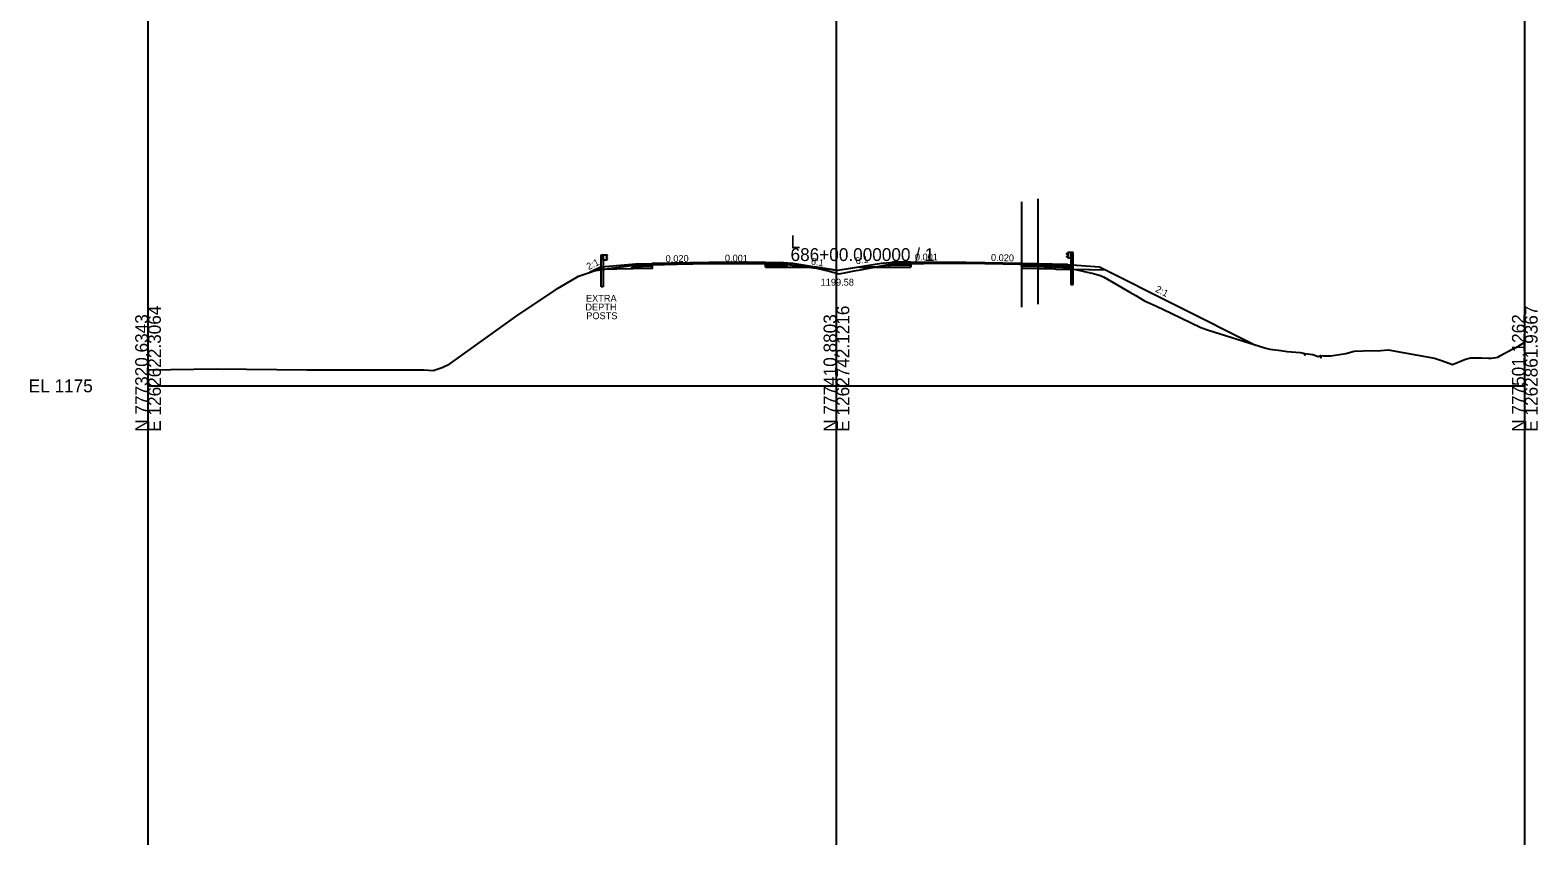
# Model space of a CAD drawing. Extents: x -41 to 1262860, y -100 to 777489.
# Drawn here: x 974.3 to 1302.8, y 1420 to 1597.5 of the extents above; entities that cross this region are included whole.
import ezdxf

# ---------------------------------------------------------------- set-up
doc = ezdxf.new("R2010")
doc.units = 0
for name, color, linetype in [('Exist Cross Section Cell', 7, 'Continuous'), ('Exist XS Center Line Elevation Label', 7, 'Continuous'), ('Exist XS Ground Line', 7, 'Continuous'), ('Prop CMT Guardrail Graphics', 7, 'Continuous'), ('Prop CMT Pvmt Course 1', 7, 'Continuous'), ('Prop CMT Pvmt Surface', 7, 'Continuous'), ('Prop CMT Shld Paved Course 1', 7, 'Continuous'), ('Prop CMT Shld Paved Course 2', 7, 'Continuous'), ('Prop CMT Shld Paved Course 4', 7, 'Continuous'), ('Prop CMT Subgrade Earthwork', 7, 'Continuous'), ('Prop XS Earthwork Shape', 7, 'Continuous'), ('Prop XS Exc Vertical Line 1', 7, 'Continuous'), ('Prop XS Exc Vertical Line 2', 7, 'Continuous'), ('Prop XS Exc Vertical Line 3', 7, 'Continuous'), ('Prop XS Finish Grade', 7, 'Continuous'), ('Prop XS SE Text', 7, 'Continuous'), ('Prop XS Side Slope Text', 7, 'Continuous'), ('Scratch_Level_4', 7, 'Continuous'), ('Scratch_Level_5', 7, 'Continuous'), ('Scratch_Level_6', 7, 'Continuous')]:
    doc.layers.add(name, color=color, linetype=linetype)

msp = doc.modelspace()

# ---------------------------------------------------------------- linework, layer by layer
at = {"layer": 'Exist Cross Section Cell'}
for p, q in [((1150, 1520), (1150, 1550)), ((1000, 1520), (1150, 1520)), ((1150, 1520), (1300, 1520))]:
    msp.add_line(p, q, dxfattribs=at)
at = {"layer": 'Exist XS Ground Line'}
msp.add_lwpolyline([(1000, 1523.52), (1014.89, 1523.69), (1034.6, 1523.51), (1050.58, 1523.5), (1054.75, 1523.49), (1060.08, 1523.5), (1062.13, 1523.37), (1064.09, 1523.99), (1065.77, 1524.78), (1080.68, 1535.47), (1088.2, 1540.49), (1089.2, 1541.22), (1090.99, 1542.24), (1093.82, 1543.89), (1096.6, 1544.85), (1096.9, 1544.96), (1097, 1545), (1097.2, 1545.06), (1097.31, 1545.09), (1097.57, 1545.12), (1100.35, 1545.57), (1106.5, 1546.38), (1107.09, 1546.45), (1107.31, 1546.47), (1110.54, 1546.67), (1122.19, 1546.77), (1123.14, 1546.78), (1123.2, 1546.78), (1124.2, 1546.76), (1135.29, 1546.61), (1138.82, 1546.44), (1139.36, 1546.42), (1141.31, 1546.18), (1145.65, 1545.64), (1148.41, 1544.97), (1150.56, 1544.44), (1152.12, 1544.72), (1153.88, 1545.04), (1155.26, 1545.27), (1157.48, 1545.69), (1160.04, 1546.18), (1161.25, 1546.4), (1161.9, 1546.43), (1165.65, 1546.62), (1175.84, 1546.78), (1177.54, 1546.8), (1179.31, 1546.76), (1189.87, 1546.5), (1192.57, 1546.33), (1193.14, 1546.29), (1195.25, 1545.93), (1197.87, 1545.45), (1200.29, 1545.43), (1202.07, 1545.38), (1205.26, 1544.64), (1205.69, 1544.56), (1207.23, 1544.12), (1207.52, 1544.05), (1207.81, 1543.9), (1208.17, 1543.75), (1213.92, 1540.41), (1215.24, 1539.71), (1217.13, 1538.56), (1219.71, 1537.34), (1222.95, 1535.84), (1229.4, 1532.71), (1231.04, 1532.12), (1243.54, 1528.22), (1244.43, 1528.01), (1246.87, 1527.73), (1248.25, 1527.52), (1251.04, 1527.24), (1251.77, 1527.11), (1252.01, 1527.08), (1252.05, 1526.66), (1252.06, 1526.7), (1252.08, 1526.66), (1252.1, 1527.07), (1253.82, 1526.87), (1254.96, 1526.42), (1255.49, 1526.61), (1255.53, 1526.1), (1255.57, 1526.6), (1256.11, 1526.53), (1257.7, 1526.54), (1261.02, 1527.08), (1262.82, 1527.54), (1266.72, 1527.71), (1267.84, 1527.66), (1270.26, 1527.85), (1280.34, 1526.03), (1282.03, 1525.47), (1284.24, 1524.66), (1287.08, 1525.82), (1288.14, 1526.12), (1290.56, 1526.1), (1292.12, 1526), (1292.76, 1526.05), (1294.12, 1526.23), (1294.71, 1526.63), (1297.41, 1528.04), (1298.08, 1528.37), (1299.97, 1529.51), (1300, 1529.53)], dxfattribs=at)
at = {"layer": 'Prop CMT Guardrail Graphics'}
for p, q in [((1098.7, 1548.58), (1099.19, 1548.58)), ((1098.7, 1546.08), (1098.7, 1548.58)), ((1099.19, 1547.4), (1099.19, 1548.58)), ((1099.19, 1548.58), (1099.86, 1548.58)), ((1099.19, 1548.58), (1099.19, 1546.07)), ((1099.86, 1547.4), (1099.19, 1547.4)), ((1099.86, 1548.58), (1099.86, 1547.4)), ((1099.86, 1548.5), (1099.86, 1547.48)), ((1099.95, 1548.48), (1099.86, 1548.5)), ((1099.86, 1547.48), (1099.95, 1547.5)), ((1099.87, 1548.04), (1100.1, 1548.24)), ((1099.87, 1547.95), (1099.87, 1548.04)), ((1100.1, 1547.75), (1099.87, 1547.95)), ((1100.1, 1548.38), (1099.95, 1548.48)), ((1099.95, 1547.5), (1100.1, 1547.6)), ((1100.1, 1548.24), (1100.1, 1548.38)), ((1100.1, 1547.6), (1100.1, 1547.75)), ((1200.18, 1548.86), (1200.32, 1548.96)), ((1200.18, 1548.72), (1200.18, 1548.86)), ((1200.41, 1548.52), (1200.18, 1548.72)), ((1200.18, 1548.22), (1200.41, 1548.43)), ((1200.18, 1548.08), (1200.18, 1548.22)), ((1200.32, 1547.98), (1200.18, 1548.08)), ((1200.32, 1548.96), (1200.42, 1548.98)), ((1200.42, 1547.96), (1200.32, 1547.98)), ((1200.41, 1548.43), (1200.41, 1548.52)), ((1200.42, 1549.06), (1200.42, 1547.88)), ((1201.09, 1549.06), (1200.42, 1549.06)), ((1200.42, 1548.98), (1200.42, 1547.96)), ((1200.42, 1547.88), (1201.09, 1547.88)), ((1201.58, 1549.06), (1201.09, 1549.06)), ((1201.09, 1547.88), (1201.09, 1549.06)), ((1201.09, 1549.06), (1201.09, 1546.55)), ((1201.58, 1546.56), (1201.58, 1549.06)), ((1098.7, 1541.57), (1098.7, 1546.08)), ((1099.19, 1546.07), (1099.19, 1541.57)), ((1201.09, 1546.55), (1201.09, 1542.05)), ((1201.58, 1542.05), (1201.58, 1546.56)), ((1099.19, 1541.57), (1098.7, 1541.57)), ((1201.09, 1542.05), (1201.58, 1542.05))]:
    msp.add_line(p, q, dxfattribs=at)
at = {"layer": 'Prop CMT Pvmt Course 1'}
for p, q in [((1134.51, 1546.65), (1138.62, 1546.66)), ((1178.3, 1546.9), (1166.23, 1546.92)), ((1178.3, 1546.65), (1166.23, 1546.67)), ((1190.37, 1546.66), (1178.3, 1546.9)), ((1178.3, 1546.9), (1178.3, 1546.9)), ((1178.3, 1546.65), (1178.3, 1546.65)), ((1190.37, 1546.41), (1178.3, 1546.65))]:
    msp.add_line(p, q, dxfattribs=at)
msp.add_lwpolyline([(1109.88, 1546.64), (1109.88, 1546.39), (1109.88, 1546.39), (1115.26, 1546.5), (1115.26, 1546.5), (1122.2, 1546.64), (1134.51, 1546.65), (1134.51, 1546.65), (1134.51, 1546.78), (1134.51, 1546.78), (1134.51, 1546.9), (1122.2, 1546.89), (1115.26, 1546.75), (1115.26, 1546.75), (1109.88, 1546.64), (1109.88, 1546.64), (1110.2, 1546.65)], dxfattribs=at)
at = {"layer": 'Prop CMT Pvmt Surface'}
for p, q in [((1106.27, 1546.57), (1109.88, 1546.64)), ((1122.2, 1546.89), (1109.88, 1546.64)), ((1134.51, 1546.9), (1122.2, 1546.89)), ((1134.51, 1546.9), (1138.37, 1546.91)), ((1166.23, 1546.92), (1162.3, 1546.92)), ((1166.23, 1546.92), (1178.3, 1546.9)), ((1178.3, 1546.9), (1190.37, 1546.66)), ((1200.37, 1546.46), (1190.37, 1546.66))]:
    msp.add_line(p, q, dxfattribs=at)
at = {"layer": 'Prop CMT Shld Paved Course 1'}
for p, q in [((1134.51, 1546.9), (1134.51, 1546.9)), ((1134.51, 1546.9), (1134.51, 1546.9)), ((1134.51, 1546.9), (1134.51, 1546.65)), ((1138.62, 1546.66), (1138.37, 1546.91)), ((1162.3, 1546.92), (1162.05, 1546.67)), ((1166.23, 1546.67), (1162.05, 1546.67)), ((1166.23, 1546.92), (1166.23, 1546.92)), ((1166.23, 1546.92), (1166.23, 1546.92)), ((1166.23, 1546.92), (1166.23, 1546.67)), ((1166.23, 1546.92), (1166.23, 1546.92)), ((1190.37, 1546.66), (1190.37, 1546.66)), ((1190.37, 1546.66), (1190.37, 1546.66)), ((1190.37, 1546.66), (1190.37, 1546.41)), ((1190.37, 1546.41), (1190.37, 1546.41)), ((1190.37, 1546.41), (1200.63, 1546.2)), ((1200.63, 1546.2), (1200.37, 1546.46))]:
    msp.add_line(p, q, dxfattribs=at)
msp.add_lwpolyline([(1106.27, 1546.57), (1109.88, 1546.64), (1109.88, 1546.64), (1109.88, 1546.39), (1106.02, 1546.31), (1106.02, 1546.31), (1106.02, 1546.31), (1106.27, 1546.57), (1106.27, 1546.57)], dxfattribs=at)
at = {"layer": 'Prop CMT Shld Paved Course 2'}
for p, q in [((1134.51, 1546.65), (1134.51, 1546.32)), ((1134.51, 1546.32), (1138.95, 1546.33)), ((1138.95, 1546.33), (1138.62, 1546.66)), ((1161.72, 1546.34), (1162.05, 1546.67)), ((1161.72, 1546.34), (1166.23, 1546.33)), ((1166.23, 1546.67), (1166.23, 1546.33)), ((1168.47, 1546.66), (1166.23, 1546.63)), ((1190.37, 1546.41), (1190.37, 1546.41)), ((1190.37, 1546.41), (1190.37, 1546.41)), ((1190.37, 1546.41), (1190.37, 1546.07)), ((1190.37, 1546.07), (1190.37, 1546.07)), ((1190.37, 1546.07), (1200.97, 1545.86)), ((1200.97, 1545.86), (1200.63, 1546.2))]:
    msp.add_line(p, q, dxfattribs=at)
msp.add_lwpolyline([(1106.02, 1546.31), (1109.88, 1546.39), (1109.88, 1546.39), (1109.88, 1546.06), (1105.68, 1545.97), (1105.68, 1545.97), (1105.68, 1545.97), (1106.02, 1546.31), (1106.02, 1546.31)], dxfattribs=at)
at = {"layer": 'Prop CMT Shld Paved Course 4'}
for p, q in [((1134.51, 1546.32), (1134.51, 1545.86)), ((1134.51, 1545.86), (1139.57, 1545.87)), ((1139.41, 1545.87), (1138.95, 1546.33)), ((1161.26, 1545.88), (1161.72, 1546.34)), ((1161.26, 1545.88), (1166.23, 1545.88)), ((1166.23, 1546.33), (1166.23, 1545.88)), ((1190.37, 1546.07), (1190.37, 1546.07)), ((1190.37, 1546.07), (1190.37, 1546.07)), ((1190.37, 1546.07), (1190.37, 1545.62)), ((1190.37, 1545.62), (1205.31, 1545.32)), ((1201.43, 1545.4), (1200.97, 1545.86))]:
    msp.add_line(p, q, dxfattribs=at)
msp.add_lwpolyline([(1105.68, 1545.97), (1109.88, 1546.06), (1109.88, 1546.06), (1109.88, 1545.6), (1105.21, 1545.5), (1105.21, 1545.5), (1105.21, 1545.5), (1105.68, 1545.97), (1105.68, 1545.97), (1105.68, 1545.97), (1105.68, 1545.97)], dxfattribs=at)
at = {"layer": 'Prop CMT Subgrade Earthwork'}
for p, q in [((1109.88, 1545.6), (1097.48, 1545.35)), ((1109.88, 1546.63), (1109.88, 1545.6)), ((1134.51, 1545.86), (1134.51, 1546.62)), ((1134.51, 1545.86), (1145.67, 1545.88)), ((1155.04, 1545.89), (1166.23, 1545.88)), ((1166.23, 1545.88), (1166.23, 1546.63)), ((1190.37, 1545.62), (1190.37, 1546.47)), ((1190.37, 1545.62), (1208.65, 1545.25))]:
    msp.add_line(p, q, dxfattribs=at)
at = {"layer": 'Prop XS Earthwork Shape'}
for points in [[(1096.9, 1544.96), (1097, 1545), (1097.2, 1545.06), (1097.31, 1545.09), (1097.57, 1545.12), (1099.2, 1545.38), (1097.48, 1545.35), (1096.22, 1544.72), (1096.6, 1544.85)], [(1106.02, 1546.31), (1105.21, 1545.5), (1099.2, 1545.38), (1100.35, 1545.57)], [(1109.88, 1545.6), (1105.21, 1545.5), (1106.02, 1546.31), (1106.5, 1546.38), (1107.09, 1546.45), (1107.31, 1546.47), (1109.88, 1546.63)], [(1134.51, 1545.86), (1134.51, 1546.62), (1135.29, 1546.61), (1138.82, 1546.44), (1138.83, 1546.44), (1139.41, 1545.87)], [(1139.41, 1545.87), (1143.75, 1545.87), (1141.31, 1546.18), (1139.36, 1546.42), (1138.83, 1546.44)], [(1148.41, 1544.97), (1150.56, 1544.44), (1152.12, 1544.72), (1153.88, 1545.04), (1155.26, 1545.27), (1157.48, 1545.69), (1158.5, 1545.89), (1155.04, 1545.89), (1150.31, 1545.1), (1145.67, 1545.88), (1143.75, 1545.87), (1145.65, 1545.64)], [(1158.5, 1545.89), (1161.26, 1545.88), (1161.81, 1546.43), (1161.25, 1546.4), (1160.04, 1546.18)], [(1166.23, 1545.88), (1166.23, 1546.63), (1165.65, 1546.62), (1161.9, 1546.43), (1161.81, 1546.43), (1161.26, 1545.88)], [(1200.29, 1545.43), (1201.43, 1545.4), (1199.28, 1545.44)]]:
    msp.add_lwpolyline(points, close=True, dxfattribs=at)
at = {"layer": 'Prop XS Exc Vertical Line 1'}
msp.add_line((1000, 1420), (1000, 1620), dxfattribs=at)
at = {"layer": 'Prop XS Exc Vertical Line 2'}
msp.add_line((1150, 1420), (1150, 1620), dxfattribs=at)
at = {"layer": 'Prop XS Exc Vertical Line 3'}
msp.add_line((1300, 1420), (1300, 1620), dxfattribs=at)
at = {"layer": 'Prop XS Finish Grade'}
for p, q in [((1098.7, 1545.96), (1096.22, 1544.72)), ((1098.7, 1545.96), (1106.27, 1546.57)), ((1106.27, 1546.57), (1105.21, 1545.5)), ((1138.37, 1546.91), (1140.51, 1546.74)), ((1138.37, 1546.91), (1139.41, 1545.87)), ((1140.51, 1546.74), (1150.31, 1545.1)), ((1150, 1545.02), (1150, 1545.02)), ((1150, 1545.02), (1150, 1545.02)), ((1160.23, 1546.76), (1150.31, 1545.1)), ((1160.23, 1546.76), (1162.3, 1546.92)), ((1162.3, 1546.92), (1161.26, 1545.88)), ((1200.37, 1546.46), (1207.35, 1545.9)), ((1200.37, 1546.46), (1201.43, 1545.4)), ((1207.35, 1545.9), (1241.35, 1528.9))]:
    msp.add_line(p, q, dxfattribs=at)
at = {"layer": 'Scratch_Level_4'}
msp.add_line((1300, 1420), (1300, 1620), dxfattribs=at)
at = {"layer": 'Scratch_Level_5'}
for p, q in [((1150, 1537.79), (1150, 1560.75)), ((1193.99, 1537.79), (1193.99, 1560.75)), ((1190.37, 1537.16), (1190.37, 1560.12))]:
    msp.add_line(p, q, dxfattribs=at)
at = {"layer": 'Scratch_Level_6'}
msp.add_line((1000, 1420), (1000, 1620), dxfattribs=at)

# ---------------------------------------------------------------- texts
at = {"layer": 'Exist Cross Section Cell'}
for s, p in [('L', (1140, 1550)), ('686+00.000000 / 1', (1140, 1547.2)), ('EL 1175', (974, 1518.6))]:
    msp.add_text(s, height=2.8, dxfattribs=at).set_placement(p)
for s, p in [('N 777320.6343', (1000, 1510)), ('E 1262622.3064', (1002.8, 1510)), ('N 777410.8803', (1150, 1510)), ('E 1262742.1216', (1152.8, 1510)), ('N 777501.1262', (1300, 1510)), ('E 1262861.9367', (1302.8, 1510))]:
    msp.add_text(s, height=2.8, rotation=90, dxfattribs=at).set_placement(p)
at = {"layer": 'Exist XS Center Line Elevation Label'}
msp.add_text('1199.58', height=1.5, dxfattribs=at).set_placement((1146.56, 1541.83))
at = {"layer": 'Prop XS SE Text'}
for s, rotation, p in [('0.020', 1.1458, (1112.79, 1546.94)), ('0.001', 359.3261, (1125.69, 1547.1)), ('0.001', 0.2069, (1167.1, 1547.32)), ('0.020', 358.8542, (1183.66, 1547.22))]:
    msp.add_text(s, height=1.5, rotation=rotation, dxfattribs=at).set_placement(p)
for s, p in [('DEPTH', (1095.29, 1536.43)), ('EXTRA', (1095.42, 1538.33)), ('POSTS', (1095.48, 1534.53))]:
    msp.add_text(s, height=1.5, dxfattribs=at).set_placement(p)
at = {"layer": 'Prop XS Side Slope Text'}
for s, rotation, p in [('2:1', 26.5651, (1095.98, 1545.21)), ('6:1', 350.5377, (1144.37, 1546.46)), ('6:1', 9.4623, (1154.28, 1546.45)), ('2:1', 333.4349, (1219.36, 1540.58))]:
    msp.add_text(s, height=1.5, rotation=rotation, dxfattribs=at).set_placement(p)

doc.saveas('drawing.dxf')
